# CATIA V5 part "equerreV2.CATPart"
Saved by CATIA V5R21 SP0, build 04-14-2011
Part number: equerre
Bounding box of the stored display mesh (mm): x -0.995 to 17.005, y -11.441 to 6.559, z -15 to 3
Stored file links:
  C:\Users\2027.DESARCY-LEMIE30\Desktop\Assemblage26.05\equerreV2.CATPart
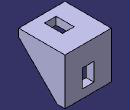
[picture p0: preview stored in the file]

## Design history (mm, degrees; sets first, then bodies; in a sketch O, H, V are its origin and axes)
Body1 (main body)
  Sketch1 on xy-plane, origin (0, 0, 0), H (1, 0, 0), V (0, 1, 0)
    line L1 (-0.9951, 6.5593) -> (17.0049, 6.5593)
    line L2 (17.0049, 6.5593) -> (17.0049, -11.4407)
    line L3 (17.0049, -11.4407) -> (-0.9951, -11.4407)
    line L4 (-0.9951, -11.4407) -> (-0.9951, 6.5593)
    length L2 = 18
    length L1 = 18
    horizontal: L1 H, L3 H
    vertical: L2 V, L4 V
  Pad1: profile Sketch1, direction (0, 0, 1), length 3
  Sketch2 on start face of Pad1, origin (0, 0, 0), H (1, 0, 0), V (0, -1, 0)
    point P1 (17.0049, -3.5593)
    reference projected line E1 (17.0049, 11.4407) -> (17.0049, -6.5593) from edge [start face of Pad1 | face of Pad1 from Sketch1.L2]
    reference projected point E2 (17.0049, -6.5593) from vertex [face of Pad1 from Sketch1.L1 | start face of Pad1 | face of Pad1 from Sketch1.L2]
    line L1 (17.0049, -3.5593) -> (17.0049, -6.5593)
    line L2 (17.0049, -3.5593) -> (-0.9951, -3.5593)
    line L3 (17.0049, -6.5593) -> (-0.9951, -6.5593)
    line L4 (-0.9951, -3.5593) -> (-0.9951, -6.5593)
    distance P1 E2 = 3
    length L2 = 18
    coincidence: P1 E1
    vertical: L1 V, L4 V
    horizontal: L2 H, L3 H
  Pad2: profile Sketch2, direction (0, 0, -1), length 15
  Sketch3 on face of Pad2, origin (17.0049, 0, 0), H (0, 1, 0), V (0, 0, 1)
    point P1 (3.5593, -15)
    point P2 (3.5593, 0)
    point P3 (-11.4407, 0)
    reference projected point E1 (-11.4407, 0) from vertex [face of Pad1 from Sketch1.L2 | start face of Pad1 | face of Pad1 from Sketch1.L3]
    reference projected point E2 (3.5593, 0) from vertex [start face of Pad1 | face of Pad2 | face of Pad2 from Sketch2.L2]
    reference projected point E3 (3.5593, -15) from vertex [face of Pad2 from Sketch2.L1 | end face of Pad2 | face of Pad2 from Sketch2.L2]
    line L1 (-11.4407, 0) -> (3.5593, 0)
    line L2 (3.5593, 0) -> (3.5593, -15)
    line L3 (-11.4407, 0) -> (3.5593, -15)
    coincidence: E1 P3, E2 P2, P1 E3
    horizontal: L1 H
    vertical: L2 V
  Pad3: profile Sketch3, direction (-1, 0, 0), length 3
  Sketch4 on face of Pad2, origin (-0.9951, 0, 0), H (0, -1, 0), V (0, 0, 1)
    point P1 (-3.5593, 0)
    point P2 (11.4407, 0)
    point P3 (-3.5593, -15)
    reference projected point E1 (-3.5593, 0) from vertex [start face of Pad1 | face of Pad2 | face of Pad2 from Sketch2.L2]
    reference projected point E2 (11.4407, 0) from vertex [face of Pad1 from Sketch1.L3 | start face of Pad1 | face of Pad1 from Sketch1.L4]
    reference projected point E3 (-3.5593, -15) from vertex [face of Pad2 from Sketch2.L4 | end face of Pad2 | face of Pad2 from Sketch2.L2]
    line L1 (-3.5593, 0) -> (11.4407, 0)
    line L2 (11.4407, 0) -> (-3.5593, -15)
    line L3 (-3.5593, 0) -> (-3.5593, -15)
    coincidence: E1 P1, E2 P2, E3 P3
    horizontal: L1 H
    vertical: L3 V
  Pad4: profile Sketch4, direction (1, 0, 0), length 3
  Sketch5 on start face of Pad1, origin (0, 0, 0), H (1, 0, 0), V (0, -1, 0)
    point P1 (10.2549, 8.1407)
    point P2 (5.7549, 8.1407)
    point P3 (10.2549, 1.1407)
    reference projected line E1 (-0.9951, -6.5593) -> (17.0049, -6.5593) from edge [face of Pad2 | end face of Pad2]
    reference projected line E2 (17.0049, 11.4407) -> (17.0049, -3.5593) from edge [face of Pad3 from Sketch3.L3 | face of Pad3]
    reference projected line E3 (-0.9951, -3.5593) -> (-0.9951, 11.4407) from edge [face of Pad4 from Sketch4.L2 | face of Pad4]
    line L1 (5.7549, 8.1407) -> (10.2549, 8.1407)
    line L2 (10.2549, 8.1407) -> (10.2549, 1.1407)
    line L3 (10.2549, 1.1407) -> (5.7549, 1.1407)
    line L4 (5.7549, 1.1407) -> (5.7549, 8.1407)
    distance P1 E1 = 14.7
    distance P1 E2 = 6.75
    distance P2 E3 = 6.75
    distance P3 P1 = 7
    horizontal: L1 H, L3 H
    vertical: L2 V, L4 V
  Pocket1: profile Sketch5, direction (0, 0, 1), length 3
  Sketch6 on face of Pad2 from Sketch2.L2, origin (0, 3.5593, 0), H (1, 0, 0), V (0, 0, 1)
    point P1 (5.7549, -4.7)
    point P2 (10.2549, -4.7)
    point P3 (5.7549, -11.7)
    reference projected line E1 (-0.9951, 3) -> (17.0049, 3) from edge [face of Pad1 from Sketch1.L3 | end face of Pad1]
    reference projected line E2 (17.0049, 0) -> (17.0049, -15) from edge [face of Pad3 from Sketch3.L3 | face of Pad3]
    reference projected line E3 (-0.9951, -15) -> (-0.9951, 0) from edge [face of Pad4 from Sketch4.L2 | face of Pad4]
    line L1 (5.7549, -4.7) -> (10.2549, -4.7)
    line L2 (5.7549, -11.7) -> (10.2549, -11.7)
    line L3 (5.7549, -4.7) -> (5.7549, -11.7)
    line L4 (10.2549, -4.7) -> (10.2549, -11.7)
    distance P3 E1 = 14.7
    distance P2 E2 = 6.75
    distance P1 E3 = 6.75
    distance P1 P3 = 7
    horizontal: L1 H, L2 H
    vertical: L3 V, L4 V
  Pocket2: profile Sketch6, direction (0, 1, 0), length 3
